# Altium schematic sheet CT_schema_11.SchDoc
size 281 x 153 mm
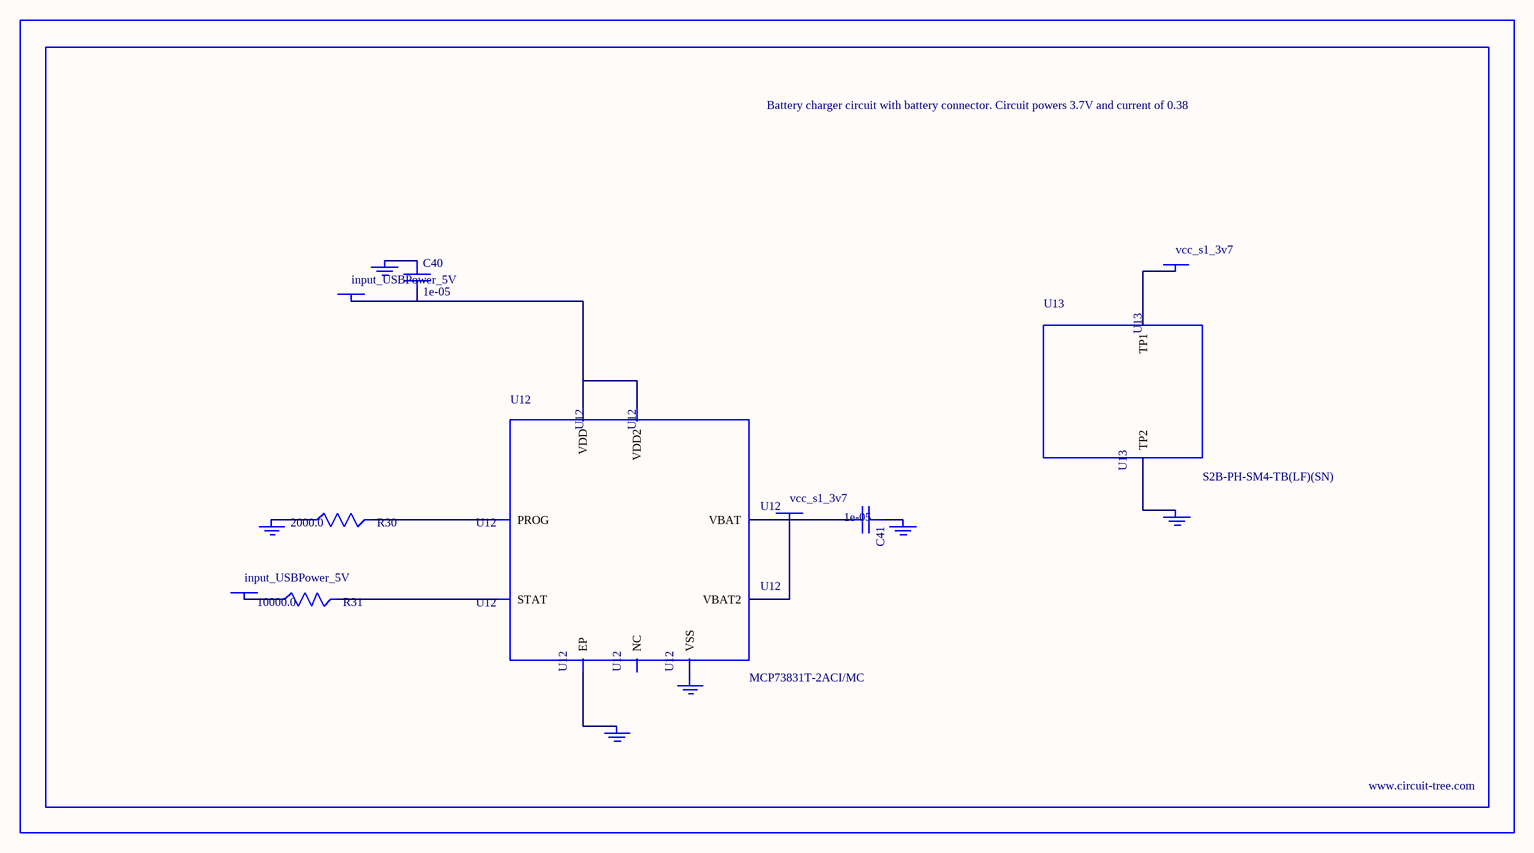
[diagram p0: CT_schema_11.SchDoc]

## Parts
BORDER10  (no value)
C40  1e-05  [C1206]
C41  1e-05  [C1206]
GND_INSTANCE_10_0  (no value)
GND_INSTANCE_10_1  (no value)
GND_INSTANCE_10_2  (no value)
GND_INSTANCE_10_3  (no value)
GND_INSTANCE_10_4  (no value)
GND_INSTANCE_10_5  (no value)
POWER_INSTANCE_10_0  input_USBPower_5V
POWER_INSTANCE_10_1  input_USBPower_5V
POWER_INSTANCE_10_2  vcc_s1_3v7
POWER_INSTANCE_10_3  vcc_s1_3v7
R30  2000.0  [R0603]
R31  10000.0  [R0603]
U12  MCP73831T-2ACI/MC  [DFN8_2X3MC]
U13  S2B-PH-SM4-TB(LF)(SN)  [JST-2-SMD]

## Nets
NetC40_1: C40.1 GND_INSTANCE_10_0.0(GND)
NetC40_2: C40.2 POWER_INSTANCE_10_0.0(PWR) U12.1(VDD) U12.2(VDD2)
NetC41_1: C41.1 GND_INSTANCE_10_1.0(GND)
NetC41_2: C41.2 POWER_INSTANCE_10_2.0(PWR) U12.3(VBAT) U12.4(VBAT2)
NetGND_INSTANCE_10_2_0: GND_INSTANCE_10_2.0(GND) R30.1
NetGND_INSTANCE_10_3_0: GND_INSTANCE_10_3.0(GND) U12.9(EP)
NetGND_INSTANCE_10_4_0: GND_INSTANCE_10_4.0(GND) U12.6(VSS)
NetGND_INSTANCE_10_5_0: GND_INSTANCE_10_5.0(GND) U13.2(TP2)
NetPOWER_INSTANCE_10_1_0: POWER_INSTANCE_10_1.0(PWR) R31.1
NetPOWER_INSTANCE_10_3_0: POWER_INSTANCE_10_3.0(PWR) U13.1(TP1)
NetR30_2: R30.2 U12.8(PROG)
NetR31_2: R31.2 U12.5(STAT)

Not connected (* = marked no-connect by the designer): U12 7(NC)

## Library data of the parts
BORDER10 = BORDER_PAGE10
C40 C41 = C1206C106K3RACTU
GND_INSTANCE_10_0-GND_INSTANCE_10_5 = GND
POWER_INSTANCE_10_0-POWER_INSTANCE_10_3 = PWR
R30 = RC0603JR-072KL
R31 = RC0603JR-0710KL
